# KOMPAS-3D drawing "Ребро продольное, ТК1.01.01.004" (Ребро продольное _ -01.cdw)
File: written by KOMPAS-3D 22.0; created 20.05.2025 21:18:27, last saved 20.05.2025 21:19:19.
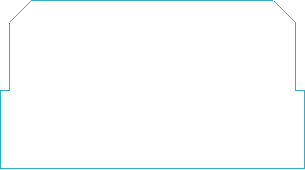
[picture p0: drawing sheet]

Sheet 1: A4, portrait

Document properties: Автор: user; Масса: 0.574941; Полное имя файла: ..\Ребро продольное.m3d

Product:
- Part/product: Ребро продольное  | designation ТК1.01.01.004
    Масса: 0.575358
    Форматы листов документа: A3
- Part/product: Ребро продольное  | designation ТК1.01.01.004-01
    Масса: 0.574941
    Форматы листов документа: A4
    source file: ..\Ребро продольное _ -01.cdw

Title block, sheet 1: Наименование: Ребро продольное; Материал: Сталь 10 ГОСТ 1050-2013; Масса: 0,55; Количество листов документа: 1; Форматы листов документа: A4

Views: Вид 1, Слева
Referenced files in D:\Работа\2025\5. Май\Задание №6 - Тележка для крыши\3Д\Тележка в сборе\Корпус тележки\: Ребро продольное.m3d
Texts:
  ТК1.01.01.004 - 01
  Без оформления
  ТК1.01.01.004
  ТК1.01.01.004-01 Ребро продольное
Dimensions and other numbers on the sheet: 1:1; 1; 0,55; 01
